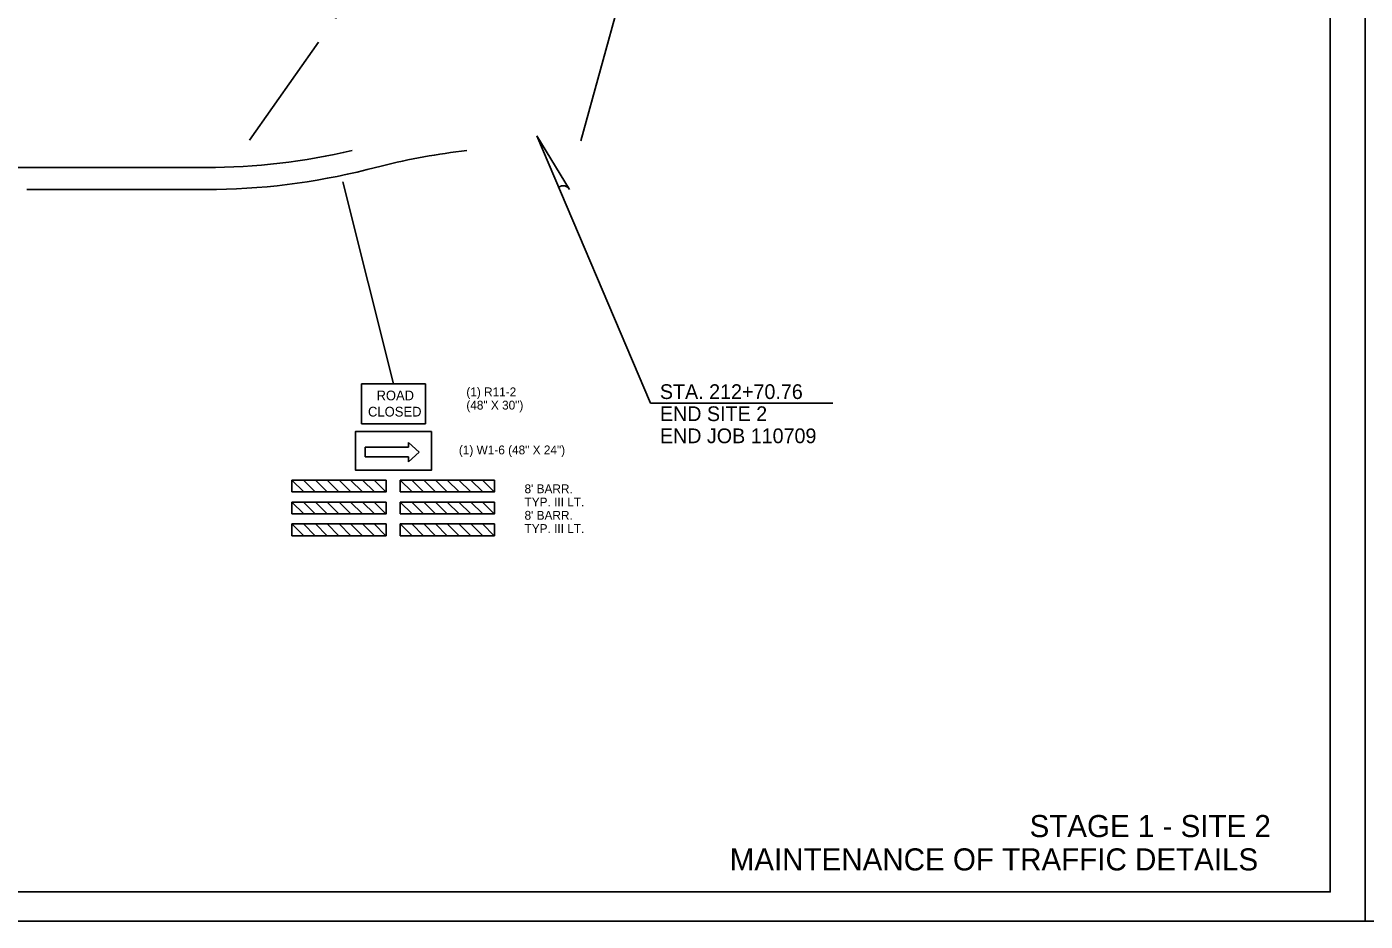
# Model space of a CAD drawing. Extents: x 2829243 to 2838161, y 467639 to 474695.
# Drawn here: x 2830244 to 2831153, y 470445 to 471052 of the extents above; entities that cross this region are included whole.
import ezdxf

# ---------------------------------------------------------------- set-up
doc = ezdxf.new("R2010")
doc.units = 0
for name, color, linetype in [('R_Border', 7, 'Continuous'), ('R_Dimension', 7, 'Continuous'), ('R_MOT', 7, 'Continuous'), ('R_No Plot', 7, 'Continuous')]:
    doc.layers.add(name, color=color, linetype=linetype)

msp = doc.modelspace()

# ---------------------------------------------------------------- linework, layer by layer
at = {"layer": 'R_Border'}
for q in [(2831129.14, 471492.28), (2829548.24, 470464.98)]:
    msp.add_line((2831129.14, 470464.98), q, dxfattribs=at)
at = {"layer": 'R_Dimension'}
for p, q in [((2830612.67, 470941.84), (2830590.32, 470978.41)), ((2830667.64, 470796.92), (2830590.32, 470978.41)), ((2830667.64, 470796.92), (2830791.36, 470796.92))]:
    msp.add_line(p, q, dxfattribs=at)
msp.add_arc((2830608.15, 470939.26), 5.2, 29.69856, 124.87266, dxfattribs=at)
at = {"layer": 'R_MOT'}
for p, q in [((2830458.64, 470947.07), (2830493.07, 470810.01)), ((2830471.34, 470782.86), (2830471.34, 470810.01)), ((2830471.34, 470810.01), (2830514.8, 470810.01)), ((2830514.8, 470782.86), (2830514.8, 470810.01)), ((2830471.34, 470782.86), (2830514.8, 470782.86)), ((2830473.87, 470766.86), (2830503.26, 470766.86)), ((2830473.87, 470766.86), (2830473.87, 470760.32)), ((2830503.26, 470766.86), (2830503.26, 470770.13)), ((2830503.26, 470770.13), (2830510.44, 470763.59)), ((2830473.87, 470760.32), (2830503.26, 470760.32)), ((2830510.44, 470763.59), (2830503.26, 470757.04)), ((2830503.26, 470760.32), (2830503.26, 470757.04)), ((2830488.1, 470744.61), (2830424.07, 470744.61)), ((2830424.07, 470736.57), (2830424.07, 470744.61)), ((2830488.1, 470736.57), (2830488.1, 470744.61)), ((2830561.63, 470744.61), (2830497.6, 470744.61)), ((2830497.6, 470736.57), (2830497.6, 470744.61)), ((2830561.63, 470736.57), (2830561.63, 470744.61)), ((2830424.12, 470736.6), (2830424.07, 470736.65)), ((2830488.1, 470736.57), (2830424.07, 470736.57)), ((2830488.1, 470729.71), (2830424.07, 470729.71)), ((2830424.07, 470721.69), (2830424.07, 470729.71)), ((2830424.07, 470721.69), (2830424.07, 470729.71)), ((2830488.1, 470721.69), (2830488.1, 470729.71)), ((2830497.65, 470736.6), (2830497.6, 470736.65)), ((2830561.63, 470736.57), (2830497.6, 470736.57)), ((2830561.63, 470729.71), (2830497.6, 470729.71)), ((2830497.6, 470721.69), (2830497.6, 470729.71)), ((2830497.6, 470721.69), (2830497.6, 470729.71)), ((2830561.63, 470721.69), (2830561.63, 470729.71)), ((2830488.1, 470721.69), (2830424.07, 470721.69)), ((2830561.63, 470721.69), (2830497.6, 470721.69)), ((2830488.1, 470714.85), (2830424.07, 470714.85)), ((2830424.07, 470706.84), (2830424.07, 470714.85)), ((2830488.1, 470706.84), (2830488.1, 470714.85)), ((2830561.63, 470714.85), (2830497.6, 470714.85)), ((2830497.6, 470706.84), (2830497.6, 470714.85)), ((2830561.63, 470706.84), (2830561.63, 470714.85)), ((2830488.1, 470706.84), (2830424.07, 470706.84)), ((2830561.63, 470706.84), (2830497.6, 470706.84))]:
    msp.add_line(p, q, dxfattribs=at)
for points in [[(2830620.35, 470975.07), (2830660.32, 471120.5), (2830598.07, 471120.5), (2830584.04, 471153.28), (2830571.05, 471120.5), (2830497.71, 471120.5), (2830453.58, 471057.96)], [(2830442.2, 471041.84), (2830395.36, 470975.46)]]:
    msp.add_lwpolyline(points, dxfattribs=at)
for points in [[(2830518.84, 470777.63), (2830467.3, 470777.63), (2830467.3, 470751.27), (2830518.84, 470751.27)], [(2830424.07, 470744.61), (2830431.94, 470744.59), (2830439.93, 470736.6), (2830432.09, 470736.6)], [(2830440.07, 470744.61), (2830447.94, 470744.59), (2830455.93, 470736.6), (2830448.09, 470736.6)], [(2830456.07, 470744.61), (2830463.94, 470744.59), (2830471.93, 470736.6), (2830464.09, 470736.6)], [(2830472.07, 470744.61), (2830479.94, 470744.59), (2830487.93, 470736.6), (2830480.09, 470736.6)], [(2830497.6, 470744.61), (2830505.47, 470744.59), (2830513.46, 470736.6), (2830505.62, 470736.6)], [(2830513.6, 470744.61), (2830521.47, 470744.59), (2830529.46, 470736.6), (2830521.62, 470736.6)], [(2830529.6, 470744.61), (2830537.47, 470744.59), (2830545.46, 470736.6), (2830537.62, 470736.6)], [(2830545.6, 470744.61), (2830553.47, 470744.59), (2830561.46, 470736.6), (2830553.62, 470736.6)], [(2830424.07, 470729.71), (2830431.94, 470729.69), (2830439.93, 470721.69), (2830432.09, 470721.69)], [(2830440.07, 470729.71), (2830447.94, 470729.69), (2830455.93, 470721.69), (2830448.09, 470721.69)], [(2830456.07, 470729.71), (2830463.94, 470729.69), (2830471.93, 470721.69), (2830464.09, 470721.69)], [(2830472.07, 470729.71), (2830479.94, 470729.69), (2830487.93, 470721.69), (2830480.09, 470721.69)], [(2830497.6, 470729.71), (2830505.47, 470729.69), (2830513.46, 470721.69), (2830505.62, 470721.69)], [(2830513.6, 470729.71), (2830521.47, 470729.69), (2830529.46, 470721.69), (2830521.62, 470721.69)], [(2830529.6, 470729.71), (2830537.47, 470729.69), (2830545.46, 470721.69), (2830537.62, 470721.69)], [(2830545.6, 470729.71), (2830553.47, 470729.69), (2830561.46, 470721.69), (2830553.62, 470721.69)], [(2830424.07, 470714.85), (2830431.94, 470714.83), (2830439.93, 470706.84), (2830432.09, 470706.84)], [(2830440.07, 470714.85), (2830447.94, 470714.83), (2830455.93, 470706.84), (2830448.09, 470706.84)], [(2830456.07, 470714.85), (2830463.94, 470714.83), (2830471.93, 470706.84), (2830464.09, 470706.84)], [(2830472.07, 470714.85), (2830479.94, 470714.83), (2830487.93, 470706.84), (2830480.09, 470706.84)], [(2830497.6, 470714.85), (2830505.47, 470714.83), (2830513.46, 470706.84), (2830505.62, 470706.84)], [(2830513.6, 470714.85), (2830521.47, 470714.83), (2830529.46, 470706.84), (2830521.62, 470706.84)], [(2830529.6, 470714.85), (2830537.47, 470714.83), (2830545.46, 470706.84), (2830537.62, 470706.84)], [(2830545.6, 470714.85), (2830553.47, 470714.83), (2830561.46, 470706.84), (2830553.62, 470706.84)]]:
    msp.add_lwpolyline(points, close=True, dxfattribs=at)
at = {"layer": 'R_No Plot'}
for p, q in [((2830244.02, 470956.91), (2830365.85, 470956.91)), ((2830475.06, 470955.42), (2830484.76, 470957.86)), ((2830244.02, 470941.91), (2830365.85, 470941.91)), ((2829486.24, 470445.09), (2831152.9, 470445.09))]:
    msp.add_line(p, q, dxfattribs=at)
for points in [[(2829486.2, 471511.76), (2831152.9, 471511.76), (2831152.9, 470445.07), (2829486.2, 470445.07)], [(2831152.9, 471511.76), (2832819.6, 471511.76), (2832819.6, 470445.07), (2831152.9, 470445.07)], [(2830717.84, 471492.28), (2830815.94, 471492.28), (2830815.94, 471442.88), (2830896.5, 471442.88), (2831012.5, 471442.88), (2831012.5, 471321.22), (2831129.14, 471321.22), (2831129.14, 470464.98), (2829548.24, 470464.98), (2829548.24, 471492.28)]]:
    msp.add_lwpolyline(points, close=True, dxfattribs=at)
for centre, radius, start, end in [((2830244.02, 471390.15), 433.24, 256.76951, 270), ((2830365.85, 471390.15), 433.24, 270, 283.23719), ((2830590.32, 470537.67), 433.24, 96.29453, 104.10169), ((2830365.85, 471390.15), 448.24, 270, 284.10169)]:
    msp.add_arc(centre, radius, start, end, dxfattribs=at)

# ---------------------------------------------------------------- texts
at = {"layer": 'R_Border'}
for s, p in [('STAGE 1 - SITE 2 ', (2830924.99, 470502.19)), ('MAINTENANCE OF TRAFFIC DETAILS', (2830721.37, 470479.55))]:
    msp.add_text(s, height=15, dxfattribs=at).set_placement(p)
at = {"layer": 'R_Dimension'}
for s, p in [('STA. 212+70.76', (2830673.95, 470799.66)), ('END SITE 2', (2830673.95, 470784.66)), ('END JOB 110709', (2830673.95, 470769.66))]:
    msp.add_text(s, height=10, rotation=0.0006, dxfattribs=at).set_placement(p)
at = {"layer": 'R_MOT'}
for s, height, p in [('ROAD', 6.577, (2830481.57, 470798.78)), ('(1) R11-2', 6, (2830542.52, 470801.5)), ('CLOSED', 6.61, (2830475.73, 470787.76)), ('(48" X 30")', 6, (2830542.52, 470792.5)), ('(1) W1-6 (48" X 24")', 6, (2830537.45, 470762.07)), ("8' BARR.", 6, (2830582.04, 470735.69)), ('TYP. III LT.', 6, (2830582.04, 470726.69)), ("8' BARR.", 6, (2830582.04, 470717.69)), ('TYP. III LT.', 6, (2830582.04, 470708.69))]:
    msp.add_text(s, height=height, dxfattribs=at).set_placement(p)

doc.saveas('drawing.dxf')
